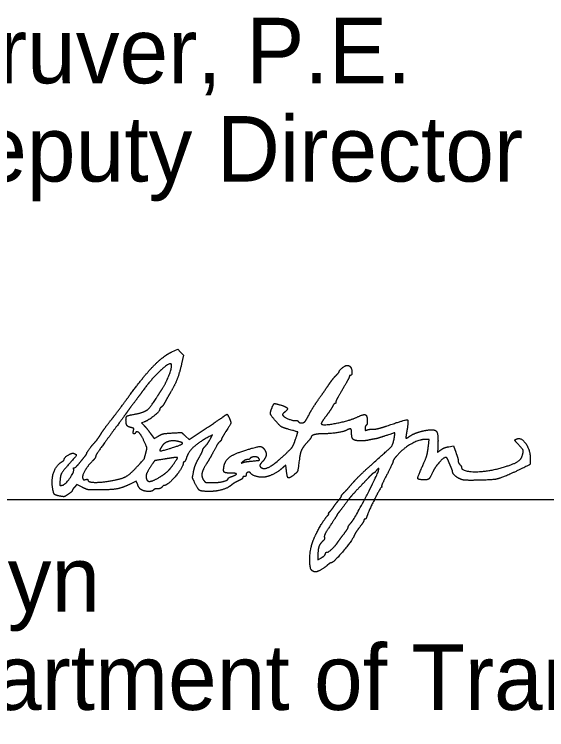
# Model space of a CAD drawing. Extents: x 0 to 44.3, y 0 to 22.
# Drawn here: x 25.676 to 26.815, y 7.305 to 8.834 of the extents above; entities that cross this region are included whole.
import ezdxf

# ---------------------------------------------------------------- set-up
doc = ezdxf.new("R2010")
doc.units = 0
doc.layers.add('SH_Data', color=7, linetype='Continuous')
doc.layers.add('SH_Text', color=7, linetype='Continuous')

msp = doc.modelspace()

# ---------------------------------------------------------------- linework, layer by layer
at = {"layer": 'SH_Data'}
msp.add_line((24.5279, 7.7968), (28.0279, 7.7968), dxfattribs=at)
at = {"layer": 'SH_Text'}
for points in [[(26.0131, 8.112), (26.0258, 8.1179), (26.0321, 8.1115), (26.0385, 8.1051), (26.0341, 8.0864)], [(25.9532, 7.962), (25.9482, 7.9605), (25.9534, 7.9553)], [(25.967, 7.9386), (25.9756, 7.9271), (25.9844, 7.9323)], [(26.0422, 7.9323), (26.0503, 7.9247), (26.0866, 7.9488)], [(26.0961, 7.9271), (26.1005, 7.935), (26.095, 7.9321)], [(26.5619, 7.9112), (26.5634, 7.925), (26.5556, 7.925)], [(26.6058, 7.9095), (26.6154, 7.9111), (26.6205, 7.8975)], [(26.2578, 7.8634), (26.2572, 7.8702), (26.2513, 7.8651)], [(25.9402, 7.8278), (25.9369, 7.8358), (25.923, 7.829)], [(25.8216, 7.8227), (25.8101, 7.8285), (25.805, 7.8227)], [(26.3256, 7.6773), (26.3256, 7.6679), (26.3331, 7.6722)]]:
    msp.add_lwpolyline(points, dxfattribs=at)
for points in [[(25.9236, 8.0201), (25.9533, 8.0607), (25.9951, 8.1036), (26.0131, 8.112)], [(26.0117, 8.0862), (26.008, 8.0899), (25.9695, 8.0541), (25.9541, 8.0328)], [(25.9934, 8.0342), (26.0028, 8.049), (26.0148, 8.0831), (26.0117, 8.0862)], [(26.0341, 8.0864), (26.0291, 8.0653), (26.0199, 8.0417), (26.0105, 8.0258)], [(26.3712, 8.0701), (26.3712, 8.0729), (26.3844, 8.0832), (26.3881, 8.0833)], [(26.3881, 8.0833), (26.3901, 8.0833), (26.3931, 8.0821), (26.3947, 8.0805)], [(26.3947, 8.0805), (26.3982, 8.077), (26.3986, 8.0618), (26.3952, 8.0618)], [(26.3508, 8.0448), (26.3547, 8.0506), (26.361, 8.0583), (26.3646, 8.062)], [(26.3646, 8.062), (26.3682, 8.0656), (26.3712, 8.0693), (26.3712, 8.0701)], [(26.3928, 8.0592), (26.3928, 8.0579), (26.3863, 8.0458), (26.3784, 8.0324)], [(26.3952, 8.0618), (26.3939, 8.0618), (26.3928, 8.0606), (26.3928, 8.0592)], [(26.3292, 8.0138), (26.3371, 8.025), (26.3468, 8.0389), (26.3508, 8.0448)], [(25.9541, 8.0328), (25.9505, 8.0279), (25.9411, 8.0152), (25.9332, 8.0047)], [(25.9829, 8.0175), (25.9861, 8.0227), (25.9909, 8.0302), (25.9934, 8.0342)], [(26.3784, 8.0324), (26.3705, 8.019), (26.364, 8.0066), (26.364, 8.0049)], [(25.8834, 7.9667), (25.8923, 7.978), (25.9104, 8.0021), (25.9236, 8.0201)], [(25.9331, 7.9788), (25.9537, 7.9826), (25.9677, 7.9935), (25.9829, 8.0175)], [(26.0105, 8.0258), (26.007, 8.0198), (26.0018, 8.0106), (25.9989, 8.0054)], [(26.3078, 7.9802), (26.3116, 7.9874), (26.3212, 8.0025), (26.3292, 8.0138)], [(25.9332, 8.0047), (25.9253, 7.9942), (25.9172, 7.9832), (25.9152, 7.9803)], [(25.9989, 8.0054), (25.9961, 8.0001), (25.9923, 7.9949), (25.9905, 7.9938)], [(26.2271, 7.992), (26.2309, 8.0011), (26.234, 8.0021), (26.2467, 7.9983)], [(26.2467, 7.9983), (26.2587, 7.9948), (26.2616, 7.9886), (26.2539, 7.9828)], [(26.362, 8.0018), (26.3609, 8.0018), (26.3585, 7.9988), (26.3567, 7.9952)], [(26.364, 8.0049), (26.364, 8.0032), (26.3631, 8.0018), (26.362, 8.0018)], [(25.9872, 7.9884), (25.9872, 7.9847), (25.9614, 7.9646), (25.9532, 7.962)], [(25.9905, 7.9938), (25.9887, 7.9928), (25.9872, 7.9904), (25.9872, 7.9884)], [(26.2369, 7.9626), (26.2254, 7.9757), (26.2232, 7.9824), (26.2271, 7.992)], [(26.2539, 7.9828), (26.2512, 7.9807), (26.2497, 7.9778), (26.2506, 7.9765)], [(26.3567, 7.9952), (26.3549, 7.9915), (26.3488, 7.9824), (26.3431, 7.975)], [(25.8619, 7.9373), (25.8648, 7.9421), (25.8745, 7.9553), (25.8834, 7.9667)], [(25.9152, 7.9803), (25.9132, 7.9773), (25.8978, 7.9564), (25.881, 7.9337)], [(25.9152, 7.9667), (25.9152, 7.9736), (25.9193, 7.9764), (25.9331, 7.9788)], [(25.9262, 7.9503), (25.919, 7.9521), (25.9152, 7.9578), (25.9152, 7.9667)], [(26.0866, 7.9488), (26.1065, 7.9621), (26.1241, 7.974), (26.1257, 7.9753)], [(26.1257, 7.9753), (26.1302, 7.9791), (26.1326, 7.9782), (26.1356, 7.9716)], [(26.1356, 7.9716), (26.14, 7.962), (26.139, 7.9579), (26.1288, 7.942)], [(26.2506, 7.9765), (26.2533, 7.9727), (26.2732, 7.9645), (26.2778, 7.9653)], [(26.2985, 7.964), (26.2998, 7.9656), (26.304, 7.9729), (26.3078, 7.9802)], [(26.3431, 7.975), (26.3374, 7.9675), (26.3328, 7.9602), (26.3328, 7.9589)], [(26.3328, 7.9589), (26.3328, 7.9536), (26.3924, 7.9646), (26.4104, 7.9731)], [(26.4104, 7.9731), (26.4233, 7.9793), (26.4312, 7.9762), (26.4312, 7.9648)], [(26.4735, 7.954), (26.5139, 7.9679), (26.5198, 7.9663), (26.5157, 7.9424)], [(25.9534, 7.9553), (25.9562, 7.9525), (25.9623, 7.945), (25.967, 7.9386)], [(26.2604, 7.9474), (26.2496, 7.9506), (26.2447, 7.9537), (26.2369, 7.9626)], [(26.2778, 7.9653), (26.2801, 7.9657), (26.2827, 7.9649), (26.2835, 7.9635)], [(26.2835, 7.9635), (26.2857, 7.96), (26.2957, 7.9603), (26.2985, 7.964)], [(26.4288, 7.955), (26.4275, 7.9541), (26.4264, 7.9513), (26.4264, 7.9487)], [(26.4312, 7.9648), (26.4312, 7.9602), (26.4301, 7.9558), (26.4288, 7.955)], [(26.4447, 7.947), (26.4489, 7.9468), (26.4618, 7.95), (26.4735, 7.954)], [(25.8456, 7.9154), (25.8522, 7.9228), (25.8564, 7.9285), (25.8619, 7.9373)], [(25.9313, 7.9441), (25.9322, 7.9476), (25.9309, 7.9491), (25.9262, 7.9503)], [(25.9355, 7.9393), (25.9331, 7.9354), (25.9299, 7.9389), (25.9313, 7.9441)], [(25.9543, 7.9207), (25.9482, 7.9344), (25.9385, 7.944), (25.9355, 7.9393)], [(25.9844, 7.9323), (25.9909, 7.9362), (25.9985, 7.9379), (26.0136, 7.9388)], [(26.0136, 7.9388), (26.0339, 7.94), (26.0341, 7.9399), (26.0422, 7.9323)], [(26.1288, 7.942), (26.1235, 7.9339), (26.1192, 7.9263), (26.1192, 7.9252)], [(26.2772, 7.9237), (26.2828, 7.9405), (26.2825, 7.9411), (26.2604, 7.9474)], [(26.3354, 7.937), (26.3239, 7.937), (26.3112, 7.9332), (26.3112, 7.9298)], [(26.3861, 7.9443), (26.3806, 7.9413), (26.3504, 7.937), (26.3354, 7.937)], [(26.3976, 7.9396), (26.3976, 7.9469), (26.3939, 7.9485), (26.3861, 7.9443)], [(26.4169, 7.922), (26.4045, 7.922), (26.3976, 7.9283), (26.3976, 7.9396)], [(26.4264, 7.9487), (26.4264, 7.9447), (26.4274, 7.9442), (26.4318, 7.9456)], [(26.4318, 7.9456), (26.4348, 7.9465), (26.4406, 7.9472), (26.4447, 7.947)], [(26.4888, 7.9274), (26.4909, 7.9389), (26.4891, 7.9393), (26.4682, 7.9321)], [(26.5157, 7.9424), (26.5143, 7.9348), (26.5136, 7.9282), (26.5141, 7.9277)], [(26.5216, 7.9316), (26.5289, 7.9366), (26.5471, 7.9429), (26.5608, 7.9451)], [(26.5608, 7.9451), (26.5754, 7.9474), (26.5831, 7.937), (26.5823, 7.9157)], [(25.881, 7.9337), (25.8643, 7.9111), (25.8505, 7.8909), (25.8504, 7.889)], [(26.0254, 7.921), (26.0145, 7.9232), (25.9971, 7.9181), (25.9928, 7.9115)], [(26.0148, 7.9075), (26.034, 7.9134), (26.038, 7.9185), (26.0254, 7.921)], [(26.095, 7.9321), (26.0716, 7.9195), (26.0488, 7.8989), (26.0447, 7.8864)], [(26.0833, 7.9089), (26.0887, 7.9149), (26.0912, 7.9185), (26.0961, 7.9271)], [(26.1192, 7.9252), (26.1192, 7.9241), (26.1176, 7.9218), (26.1156, 7.9202)], [(26.2589, 7.8964), (26.2693, 7.9064), (26.2734, 7.9126), (26.2772, 7.9237)], [(26.3112, 7.9298), (26.3112, 7.9289), (26.307, 7.9235), (26.3018, 7.9177)], [(26.4336, 7.9234), (26.4303, 7.9226), (26.4228, 7.922), (26.4169, 7.922)], [(26.4468, 7.926), (26.4428, 7.9253), (26.4369, 7.9242), (26.4336, 7.9234)], [(26.4439, 7.8744), (26.4795, 7.906), (26.4864, 7.9142), (26.4888, 7.9274)], [(26.4682, 7.9321), (26.4604, 7.9294), (26.4507, 7.9266), (26.4468, 7.926)], [(26.5556, 7.925), (26.5429, 7.925), (26.5091, 7.9065), (26.4969, 7.893)], [(26.5141, 7.9277), (26.5145, 7.9272), (26.5179, 7.929), (26.5216, 7.9316)], [(26.7524, 7.9163), (26.7471, 7.922), (26.7468, 7.9247), (26.7515, 7.9264)], [(26.7515, 7.9264), (26.76, 7.9297), (26.7785, 7.9048), (26.7795, 7.8885)], [(25.8312, 7.895), (25.8312, 7.8966), (25.8403, 7.9096), (25.8456, 7.9154)], [(25.9576, 7.8962), (25.9602, 7.906), (25.9599, 7.9082), (25.9543, 7.9207)], [(25.9928, 7.9115), (25.9858, 7.9008), (25.9903, 7.9), (26.0148, 7.9075)], [(26.0793, 7.9019), (26.0796, 7.9037), (26.0813, 7.9068), (26.0833, 7.9089)], [(26.1087, 7.9109), (26.1006, 7.8955), (26.0928, 7.8817), (26.0867, 7.872)], [(26.1156, 7.9202), (26.1137, 7.9186), (26.1106, 7.9144), (26.1087, 7.9109)], [(26.1626, 7.8992), (26.1944, 7.9098), (26.2078, 7.9102), (26.2129, 7.9008)], [(26.3018, 7.9177), (26.2933, 7.9083), (26.2876, 7.8957), (26.286, 7.883)], [(26.5472, 7.8633), (26.5563, 7.8832), (26.5603, 7.8964), (26.5619, 7.9112)], [(26.5823, 7.9157), (26.5816, 7.8973), (26.5815, 7.8976), (26.5892, 7.9031)], [(26.5892, 7.9031), (26.593, 7.9058), (26.6004, 7.9087), (26.6058, 7.9095)], [(26.7615, 7.8872), (26.7655, 7.899), (26.7639, 7.9039), (26.7524, 7.9163)], [(25.7832, 7.8829), (25.7833, 7.8867), (25.8, 7.8967), (25.8038, 7.8952)], [(25.8038, 7.8952), (25.8098, 7.8929), (25.8075, 7.888), (25.7932, 7.8721)], [(25.8167, 7.8758), (25.822, 7.8824), (25.8275, 7.8891), (25.8288, 7.8907)], [(25.8288, 7.8907), (25.8301, 7.8923), (25.8312, 7.8942), (25.8312, 7.895)], [(25.938, 7.8657), (25.9541, 7.8832), (25.9544, 7.8838), (25.9576, 7.8962)], [(26.0708, 7.8848), (26.0752, 7.8925), (26.079, 7.9002), (26.0793, 7.9019)], [(26.1249, 7.8681), (26.1271, 7.8794), (26.1433, 7.8928), (26.1626, 7.8992)], [(26.2019, 7.8675), (26.2072, 7.8589), (26.2339, 7.8724), (26.2589, 7.8964)], [(26.2129, 7.9008), (26.2161, 7.8947), (26.2127, 7.8833), (26.2053, 7.8754)], [(26.4969, 7.893), (26.4911, 7.8865), (26.4864, 7.88), (26.4864, 7.8784)], [(26.6205, 7.8975), (26.6233, 7.8901), (26.6256, 7.8819), (26.6256, 7.8794)], [(25.7583, 7.8213), (25.7554, 7.8398), (25.7661, 7.8699), (25.7785, 7.8776)], [(25.7785, 7.8776), (25.7811, 7.8792), (25.7832, 7.8816), (25.7832, 7.8829)], [(25.8044, 7.8645), (25.8058, 7.8641), (25.8113, 7.8692), (25.8167, 7.8758)], [(25.843, 7.8782), (25.8332, 7.8686), (25.8208, 7.8465), (25.8226, 7.8418)], [(25.8504, 7.889), (25.8503, 7.887), (25.847, 7.8822), (25.843, 7.8782)], [(25.9956, 7.8827), (25.9778, 7.8801), (25.9758, 7.879), (25.9685, 7.8678)], [(26.013, 7.8854), (26.0074, 7.8845), (25.9995, 7.8833), (25.9956, 7.8827)], [(26.018, 7.8737), (26.0258, 7.8851), (26.0249, 7.8872), (26.013, 7.8854)], [(26.0396, 7.877), (26.0385, 7.877), (26.0376, 7.8756), (26.0375, 7.874)], [(26.0447, 7.8864), (26.043, 7.8812), (26.0407, 7.877), (26.0396, 7.877)], [(26.0599, 7.857), (26.0615, 7.8647), (26.0664, 7.8772), (26.0708, 7.8848)], [(26.1658, 7.878), (26.1612, 7.8742), (26.1612, 7.8742), (26.166, 7.8759)], [(26.1747, 7.8818), (26.1724, 7.8818), (26.1684, 7.88), (26.1658, 7.878)], [(26.166, 7.8759), (26.1686, 7.8768), (26.1762, 7.878), (26.1828, 7.8786)], [(26.1802, 7.8839), (26.1795, 7.8827), (26.177, 7.8818), (26.1747, 7.8818)], [(26.1987, 7.885), (26.1959, 7.8884), (26.1825, 7.8876), (26.1802, 7.8839)], [(26.1828, 7.8786), (26.1995, 7.8801), (26.2019, 7.8811), (26.1987, 7.885)], [(26.2053, 7.8754), (26.2025, 7.8725), (26.201, 7.869), (26.2019, 7.8675)], [(26.286, 7.883), (26.2832, 7.8605), (26.2814, 7.855), (26.2758, 7.8505)], [(26.4864, 7.8784), (26.4864, 7.8768), (26.4804, 7.864), (26.4732, 7.8498)], [(26.5988, 7.8866), (26.5945, 7.8866), (26.5762, 7.8661), (26.5715, 7.8559)], [(26.6044, 7.88), (26.6029, 7.8836), (26.6004, 7.8866), (26.5988, 7.8866)], [(26.6103, 7.8658), (26.6085, 7.87), (26.6058, 7.8763), (26.6044, 7.88)], [(26.6256, 7.8794), (26.6256, 7.8769), (26.6272, 7.8733), (26.6292, 7.8713)], [(26.7126, 7.863), (26.7363, 7.8692), (26.7593, 7.8806), (26.7615, 7.8872)], [(26.7795, 7.8885), (26.7804, 7.8732), (26.7778, 7.8701), (26.7544, 7.8591)], [(25.7932, 7.8721), (25.7795, 7.857), (25.7745, 7.8468), (25.7739, 7.833)], [(25.7787, 7.827), (25.7851, 7.8279), (25.8052, 7.8564), (25.8032, 7.8616)], [(25.8032, 7.8616), (25.8024, 7.8635), (25.803, 7.8648), (25.8044, 7.8645)], [(25.8815, 7.8363), (25.9042, 7.84), (25.9238, 7.8502), (25.938, 7.8657)], [(25.9685, 7.8678), (25.9603, 7.8551), (25.9571, 7.8453), (25.9593, 7.8395)], [(25.9881, 7.845), (25.9993, 7.852), (26.0102, 7.8626), (26.018, 7.8737)], [(26.0375, 7.874), (26.0374, 7.8654), (26.0043, 7.8266), (25.9972, 7.8266)], [(26.0867, 7.872), (26.0787, 7.8594), (26.0765, 7.8442), (26.0816, 7.8374)], [(26.1385, 7.853), (26.127, 7.853), (26.1229, 7.8575), (26.1249, 7.8681)], [(26.2513, 7.8651), (26.2419, 7.8569), (26.2219, 7.8463), (26.2128, 7.8446)], [(26.2758, 7.8505), (26.264, 7.8413), (26.2597, 7.8444), (26.2578, 7.8634)], [(26.3973, 7.7479), (26.4049, 7.7566), (26.4582, 7.8604), (26.4561, 7.8624)], [(26.3999, 7.8317), (26.4071, 7.8401), (26.4269, 7.8593), (26.4439, 7.8744)], [(26.4561, 7.8624), (26.4554, 7.8632), (26.4528, 7.8613), (26.4504, 7.8584)], [(26.5546, 7.8386), (26.5401, 7.8386), (26.5385, 7.844), (26.5472, 7.8633)], [(26.6137, 7.8562), (26.6136, 7.8573), (26.6121, 7.8616), (26.6103, 7.8658)], [(26.6292, 7.8713), (26.6312, 7.8693), (26.6328, 7.8666), (26.6328, 7.8653)], [(26.6328, 7.8653), (26.6328, 7.8568), (26.6834, 7.8553), (26.7126, 7.863)], [(25.9593, 7.8395), (25.9614, 7.8342), (25.9749, 7.8369), (25.9881, 7.845)], [(26.0619, 7.833), (26.0575, 7.8421), (26.0573, 7.8443), (26.0599, 7.857)], [(26.1336, 7.8412), (26.1336, 7.8422), (26.1373, 7.8444), (26.1419, 7.846)], [(26.1419, 7.846), (26.1522, 7.8498), (26.1506, 7.853), (26.1385, 7.853)], [(26.1684, 7.8458), (26.1664, 7.8458), (26.1648, 7.8447), (26.1648, 7.8433)], [(26.172, 7.8491), (26.172, 7.8473), (26.1704, 7.8458), (26.1684, 7.8458)], [(26.1815, 7.8531), (26.1795, 7.8564), (26.172, 7.8532), (26.172, 7.8491)], [(26.2128, 7.8446), (26.2042, 7.8431), (26.1844, 7.8484), (26.1815, 7.8531)], [(26.4358, 7.8452), (26.4317, 7.8409), (26.4212, 7.8298), (26.4124, 7.8205)], [(26.4446, 7.853), (26.4438, 7.853), (26.4399, 7.8494), (26.4358, 7.8452)], [(26.4504, 7.8584), (26.448, 7.8554), (26.4454, 7.853), (26.4446, 7.853)], [(26.4732, 7.8498), (26.4659, 7.8357), (26.4607, 7.8241), (26.4618, 7.8241)], [(26.5715, 7.8559), (26.5658, 7.8435), (26.5609, 7.8386), (26.5546, 7.8386)], [(26.6293, 7.8406), (26.6223, 7.844), (26.6138, 7.8524), (26.6137, 7.8562)], [(26.7544, 7.8591), (26.7196, 7.8428), (26.6985, 7.838), (26.6592, 7.8376)], [(25.7739, 7.833), (25.7737, 7.8274), (25.7745, 7.8264), (25.7787, 7.827)], [(25.8226, 7.8418), (25.8235, 7.8394), (25.8258, 7.8385), (25.8288, 7.8393)], [(25.8288, 7.8393), (25.8314, 7.8399), (25.8336, 7.8396), (25.8336, 7.8385)], [(25.8336, 7.8385), (25.8336, 7.8339), (25.8592, 7.8327), (25.8815, 7.8363)], [(26.0937, 7.8138), (26.0762, 7.8139), (26.0692, 7.8182), (26.0619, 7.833)], [(26.0816, 7.8374), (26.0844, 7.8336), (26.088, 7.8326), (26.0992, 7.8326)], [(26.0992, 7.8326), (26.1132, 7.8326), (26.1336, 7.8377), (26.1336, 7.8412)], [(26.1594, 7.8384), (26.152, 7.8351), (26.1444, 7.8306), (26.1402, 7.8271)], [(26.1648, 7.8433), (26.1648, 7.8419), (26.1624, 7.8397), (26.1594, 7.8384)], [(26.3814, 7.8113), (26.3844, 7.8141), (26.3927, 7.8233), (26.3999, 7.8317)], [(26.6592, 7.8376), (26.6442, 7.8374), (26.6339, 7.8385), (26.6293, 7.8406)], [(25.7749, 7.8036), (25.764, 7.8056), (25.7602, 7.8097), (25.7583, 7.8213)], [(25.8, 7.8151), (25.8, 7.8142), (25.7962, 7.8108), (25.7916, 7.8077)], [(25.805, 7.8227), (25.8022, 7.8195), (25.8, 7.8161), (25.8, 7.8151)], [(25.8524, 7.817), (25.8368, 7.817), (25.8309, 7.8181), (25.8216, 7.8227)], [(25.923, 7.829), (25.9074, 7.8212), (25.8823, 7.817), (25.8524, 7.817)], [(25.9484, 7.8172), (25.9458, 7.8186), (25.9421, 7.8234), (25.9402, 7.8278)], [(25.974, 7.817), (25.972, 7.8138), (25.9545, 7.8139), (25.9484, 7.8172)], [(25.9822, 7.8194), (25.9785, 7.8194), (25.9748, 7.8183), (25.974, 7.817)], [(25.992, 7.823), (25.9903, 7.821), (25.9859, 7.8194), (25.9822, 7.8194)], [(25.9972, 7.8266), (25.996, 7.8266), (25.9936, 7.8249), (25.992, 7.823)], [(26.1402, 7.8271), (26.1325, 7.8207), (26.1082, 7.8138), (26.0937, 7.8138)], [(26.4124, 7.8205), (26.4036, 7.8113), (26.3937, 7.8), (26.3904, 7.7955)], [(26.461, 7.8223), (26.4583, 7.8205), (26.4331, 7.7695), (26.4301, 7.76)], [(26.4618, 7.8241), (26.4628, 7.8241), (26.4624, 7.8233), (26.461, 7.8223)], [(25.7916, 7.8077), (25.7851, 7.8032), (25.7815, 7.8023), (25.7749, 7.8036)], [(26.3694, 7.7943), (26.373, 7.7985), (26.376, 7.8029), (26.376, 7.8041)], [(26.376, 7.8041), (26.376, 7.8052), (26.3785, 7.8085), (26.3814, 7.8113)], [(26.3592, 7.7809), (26.3612, 7.784), (26.3658, 7.79), (26.3694, 7.7943)], [(26.3904, 7.7955), (26.3823, 7.7846), (26.3718, 7.7708), (26.3688, 7.7673)], [(26.3488, 7.7666), (26.3479, 7.7666), (26.3491, 7.7685), (26.3514, 7.771)], [(26.3514, 7.771), (26.3537, 7.7734), (26.3572, 7.7779), (26.3592, 7.7809)], [(26.3154, 7.7086), (26.3213, 7.7234), (26.3384, 7.7533), (26.3455, 7.7612)], [(26.3455, 7.7612), (26.3482, 7.7641), (26.3497, 7.7666), (26.3488, 7.7666)], [(26.3664, 7.7634), (26.3664, 7.7628), (26.36, 7.7529), (26.3523, 7.7413)], [(26.3688, 7.7673), (26.3675, 7.7657), (26.3664, 7.7639), (26.3664, 7.7634)], [(26.4262, 7.7546), (26.425, 7.7546), (26.424, 7.7534), (26.424, 7.7521)], [(26.4301, 7.76), (26.4292, 7.757), (26.4274, 7.7546), (26.4262, 7.7546)], [(26.3523, 7.7413), (26.3436, 7.7282), (26.3387, 7.7185), (26.3394, 7.7158)], [(26.3802, 7.7217), (26.3858, 7.7291), (26.3904, 7.7362), (26.3904, 7.7376)], [(26.3904, 7.7376), (26.3904, 7.7389), (26.3935, 7.7435), (26.3973, 7.7479)], [(26.424, 7.7521), (26.424, 7.7507), (26.4197, 7.7439), (26.4145, 7.737)], [(26.4145, 7.737), (26.4093, 7.7301), (26.4042, 7.7221), (26.4031, 7.7193)], [(26.3136, 7.6441), (26.3076, 7.6479), (26.3089, 7.6922), (26.3154, 7.7086)], [(26.3357, 7.7072), (26.3298, 7.7019), (26.3256, 7.6896), (26.3256, 7.6773)], [(26.3394, 7.7158), (26.34, 7.7132), (26.3385, 7.7096), (26.3357, 7.7072)], [(26.4031, 7.7193), (26.3994, 7.7094), (26.3583, 7.661), (26.3536, 7.661)], [(26.3676, 7.7045), (26.3689, 7.7066), (26.3746, 7.7144), (26.3802, 7.7217)], [(26.3448, 7.6838), (26.3467, 7.6826), (26.3633, 7.6977), (26.3676, 7.7045)], [(26.3331, 7.6722), (26.3373, 7.6746), (26.3412, 7.6784), (26.3418, 7.6807)], [(26.3418, 7.6807), (26.3424, 7.683), (26.3438, 7.6844), (26.3448, 7.6838)], [(26.3536, 7.661), (26.3522, 7.661), (26.3489, 7.6589), (26.3461, 7.6564)], [(26.3461, 7.6564), (26.3399, 7.6507), (26.324, 7.6417), (26.3201, 7.6418)], [(26.3201, 7.6418), (26.3185, 7.6418), (26.3156, 7.6429), (26.3136, 7.6441)]]:
    msp.add_open_spline(points, degree=2, dxfattribs=at)

# ---------------------------------------------------------------- texts
for s, p in [('Douglas A. Gruver, P.E.', (24.5279, 8.6862)), ('District       Deputy Director', (24.5279, 8.4762)), ('Pamela Boratyn', (24.5279, 7.5568)), ('Director, Department of Transportation', (24.5279, 7.3468))]:
    msp.add_text(s, height=0.14, dxfattribs=at).set_placement(p)

doc.saveas('drawing.dxf')
